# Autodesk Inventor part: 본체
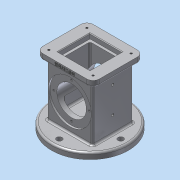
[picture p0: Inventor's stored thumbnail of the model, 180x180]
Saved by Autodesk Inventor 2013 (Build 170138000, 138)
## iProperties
Created: 2018-10
Part Number: 본체
Material: 알루미늄 6061
Document SubType Name: Modeling
Designer: dgall
Density: 2.71 g/cm^3
Mass: 988.224 g
Surface Area: 743.902 cm^2
Volume: 364.658 cm^3
Author: dgall
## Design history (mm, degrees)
sketch "스케치1"
  geometry: L1 (0, 0)-(74, 0); L2 (74, 0)-(74, 66); L3 (74, 66)-(0, 66); L4 (0, 66)-(0, 0)
  constraints: 8 end point, 2 parallel, 1 horizontal, 1 perpendicular
  dimensions: "d0" = 74 distance of L2.end L3.end; "d2" = 66 distance of L1.end L2.end
extrude "돌출1" new body sketch "스케치1" distance "d3" = 108; taper "d4" = 0 deg
sketch "스케치2"
  geometry: L1 (0, 0)-(74, 0) reference; L2 (74, 0)-(74, 66) reference; L3 (74, 66)-(0, 66) reference; L4 (0, 66)-(0, 0) reference; L5 (0, 0)-(74, 0) reference; L6 (74, 0)-(74, 66) reference; L7 (74, 66)-(0, 66) reference; L8 (0, 66)-(0, 0) reference; L9 (-9, -8)-(83, -8); L10 (83, -8)-(83, 74); L11 (83, 74)-(-9, 74); L12 (-9, 74)-(-9, -8); 4 further points
  constraints: 8 end point, 4 midpoint, 2 parallel, 1 horizontal, 1 horizontal alignment, 1 perpendicular, 1 vertical alignment
  dimensions: "d5" = 92 distance of L10.end L11.end; "d7" = 82 distance of L9.end L10.end
extrude "돌출2" join sketch "스케치2" distance "d8" = 10; taper "d9" = 0 deg
sketch "스케치4"
  geometry: L1 (0, 0)-(-74, 0) reference; L2 (0, 66)-(0, 0) reference; L3 (-74, 66)-(0, 66) reference; L4 (-74, 0)-(-74, 66) reference; L5 (0, 0)-(-74, 0) reference; L6 (0, 66)-(0, 0) reference; L7 (-74, 66)-(0, 66) reference; L8 (-74, 0)-(-74, 66) reference; L9 (-83, 74)-(-83, -8) reference; C1 r 62.5 at (-37, 33); 2 further points
  constraints: 2 midpoint, 1 centre point, 1 horizontal alignment, 1 vertical alignment
  dimensions: "d14" = 125 diameter of C1
extrude "돌출4" join sketch "스케치4" distance "d16" = 10; taper "d17" = 0 deg
sketch "스케치5"
  geometry: L1 (83, 74)-(-9, 74) reference; L2 (-9, 74)-(-9, -8) reference; L3 (11, 7)-(63, 7); L4 (63, 7)-(63, 59); L5 (63, 59)-(11, 59); L6 (11, 59)-(11, 7); L7 (15, 11)-(59, 11); L8 (59, 11)-(59, 55); L9 (59, 55)-(15, 55); L10 (15, 55)-(15, 11); 8 further points
  constraints: 16 end point, 7 midpoint, 4 parallel, 4 perpendicular, 2 horizontal, 2 horizontal alignment, 2 vertical alignment
  dimensions: "d18" = 52 distance of L4.end L5.end; "d20" = 44 distance of L8.end L9.end
extrude "돌출5" cut sketch "스케치5" distance "d21" = 82; taper "d22" = 0 deg
extrude "돌출6" cut sketch "스케치5" distance "d23" = 8; taper "d24" = 0 deg
sketch "스케치6"
  geometry: C1 r 62.5 at (0, 0) reference; C2 r 28 at (0, 0); 1 further point
  constraints: 1 centre point, 1 coincident
  dimensions: "d25" = 56 diameter of C2
extrude "돌출7" cut sketch "스케치6" distance "d27" = 18; taper "d28" = -10 deg
sketch "스케치7"
  geometry: L1 (0, -88)-(0, 0) reference; L2 (0, -88)-(74, -88) reference; L3 (74, -88)-(74, 0) reference; L4 (74, 0)-(0, 0) reference; L5 (0, -88)-(0, 0) reference; L6 (83, 0)-(-9, 0) reference; C1 r 35 at (37, -44); C2 r 24 at (37, -44); 3 further points
  constraints: 2 centre point, 2 midpoint, 1 coincident, 1 horizontal alignment, 1 vertical alignment
  dimensions: "d29" = 70 diameter of C1; "d31" = 48 diameter of C2
  node "투영된 루프4"
extrude "돌출8" cut sketch "스케치7" stored distance "d32" = 18; taper "d33" = 0 deg
extrude "돌출9" cut sketch "스케치7" distance "d34" = 3; taper "d35" = 0 deg
sketch "스케치8"
  geometry: C1 r 24 at (37, 44) reference; C2 r 35 at (37, 44); 1 further point
  constraints: 1 centre point, 1 coincident
  dimensions: "d36" = 70 diameter of C2
extrude "돌출10" cut sketch "스케치8" distance "d38" = 3; taper "d39" = 0 deg
fillet "모깎기1" dims "d40" = 3
fillet "모깎기2" dims "d41" = 10
fillet "모깎기3" dims "d42" = 3
sketch "스케치9"
  geometry: A1 r 10 centre (1, 64) between (1, 74) and (-9, 64) reference; 2 further points
  constraints: 1 coincident
hole "구멍1" sketch "스케치9" at (1, 64) diameter "d43" = 3.242; stored, may be unused: countersink angle "d47" = 90 deg, drill point angle "d49" = 118 deg; dims "d44" = 4, "d45" = 4, "d46" = 2, "d48" = 6
node "작업 평면1"
node "작업 평면2"
chamfer "모따기1" distance "d50" = 1; stored, may be unused: second distance "d51" = 2, angle "d52" = 45 deg
sketch "스케치10"
  geometry: C1 r 24 at (0, 0) reference; 2 further points
  constraints: 1 vertical alignment
  dimensions: "d53" = 29 distance of C1.centre point (0, -29)
hole "구멍2" sketch "스케치10" at (0, -29) diameter "d54" = 3.242; stored, may be unused: countersink angle "d58" = 90 deg, drill point angle "d60" = 118 deg; dims "d55" = 4, "d56" = 4, "d57" = 2, "d59" = 6
sketch "스케치11"
  geometry: L1 (95, 92.5)-(95, -32.5) reference; L2 (88, 92.5)-(88, -32.5) reference; L3 (-13, -1)-(-13, 61) reference; 5 further points
  constraints: 2 horizontal alignment, 2 midpoint
  dimensions: "d65" = 43 distance of point (58, 30) point (15, 30); "d67" = 37 distance from line of L1 point (58, 30)
hole "구멍3" sketch "스케치11" at (15, 30), (58, 30) diameter "d68" = 4.134; stored, may be unused: countersink angle "d72" = 90 deg, drill point angle "d74" = 118 deg; dims "d69" = 4, "d70" = 4, "d71" = 2, "d73" = 30
sketch "스케치12"
  geometry: C1 r 59.5 at (0, 0) reference; C2 r 4.5 at (0, 50); C3 r 4.5 at (-50, 0); C4 r 4.5 at (0, -50); C5 r 4.5 at (50, 0); A1 r 50 centre (0, 0) between (0, 50) and (-50, 0); 1 further point
  constraints: 5 centre point, 4 point on circle, 3 equal radius, 2 horizontal alignment, 2 vertical alignment, 1 coincident
  dimensions: "d75" = 9 diameter of C2; "d77" = 100 diameter of A1
extrude "돌출11" cut sketch "스케치12" stored distance "d78" = 3; taper "d79" = 0 deg
node "작업 평면3"
sketch "스케치14"
  geometry: L1 (82, 0)-(72, 0) reference; L2 (72, 0)-(72, -7) reference; L3 (82, -7)-(72, -7) reference; L4 (82, -7)-(82, 0) reference; L5 (-10, 0)-(-10, -7) reference; 2 further points
  constraints: 1 other
  dimensions: "d81" = 46 distance from line of L5 point (36, -4); "d82" = 4 distance from line of point (36, -4) L1
feature "엠보싱1" sketch "스케치14" dims "d0" = 74, "d2" = 66, "d5" = 92, "d7" = 82, "d83" = 0.5, "d84" = 0
node "솔리드1"
mirror "대칭1"
mirror "대칭2"
pattern_circular "원형 패턴1" dims angle "d62" = 360 deg
mirror "대칭3"
node "투영된 루프1"
node "투영된 루프3"
node "투영된 루프5"
node "투영된 루프6"
